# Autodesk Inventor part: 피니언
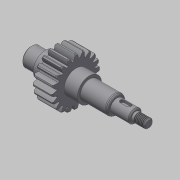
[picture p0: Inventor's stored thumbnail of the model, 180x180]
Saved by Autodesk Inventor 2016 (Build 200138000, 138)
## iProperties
Created: 2019-06
Part Number: 피니언
Material: 스테인리스강
Document SubType Name: Modeling
Designer: mduedu
Density: 1 g/cm^3
Appearance: 기본값
Author: mduedu
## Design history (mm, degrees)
sketch "스케치1"
  geometry: L1 (0, 0)-(13, 0); L2 (13, 0)-(13, 8.5); L3 (13, 8.5)-(0, 8.5); L4 (0, 8.5)-(0, 0); L5 (13, 0)-(53, 0); L6 (53, 0)-(53, 11); L7 (53, 11)-(13, 11); L8 (13, 11)-(13, 0); L9 (53, 0)-(78, 0); L10 (78, 0)-(78, 8.5); L11 (78, 8.5)-(53, 8.5); L12 (53, 8.5)-(53, 0); L13 (78, 0)-(95, 0); L14 (95, 0)-(95, 6); L15 (95, 6)-(78, 6); L16 (78, 6)-(78, 0); L17 (95, 0)-(107, 0); L18 (107, 0)-(107, 4); L19 (107, 4)-(95, 4); L20 (95, 4)-(95, 0)
  constraints: 40 end point, 10 parallel, 5 horizontal, 5 perpendicular
  dimensions: "d0" = 107 distance between parallel lines of L18 L4; "d2" = 78 distance between parallel lines of L10 L4; "d3" = 40 distance of L6.end L7.end; "d4" = 25 distance of L10.end L11.end; "d5" = 17 distance of L14.end L15.end; "d6" = 8 diameter of L19 L17; "d7" = 12 diameter of L15 L13; "d8" = 17 diameter of L11 L9; "d9" = 22 diameter of L7 L5; "d10" = 17 diameter of L3 L1
revolve "회전1" sketch "스케치1" stored, may be unused: angle "d11" = 90 deg
node "작업 평면1"
sketch "스케치2"
  geometry: C1 r 17.5 at (0, 0); C2 r 20 at (0, 0); C3 r 22 at (0, 0); 1 further point
  constraints: 3 centre point, 3 coincident
  dimensions: "d13" = 40 diameter of C2; "d15" = 44 diameter of C3; "d16" = 35 diameter of C1
extrude "돌출1" join sketch "스케치2" distance "d17" = 18; taper "d18" = 0 deg
sketch "스케치3"
  geometry: L1 (0, 0)-(22, 0); L2 (0, 0)-(0, 22); L3 (0.57, 0)-(0.57, 22); L4 (1.57, 0)-(1.57, 22); L5 (2.07, 0)-(2.07, 22); A1 r 22 centre (0, 0) between (22, 0) and (0, 22) reference; A2 r 9.495 centre (-7.411, 16.856) between (2.07, 17.377) and (0.57, 22); A3 r 9.495 centre (7.411, 16.856) between (-0.57, 22) and (-2.07, 17.377); A4 r 17.5 centre (0, 0) between (2.07, 17.377) and (-2.07, 17.377); A5 r 22.007 centre (0, 0) between (0.57, 22) and (-0.57, 22); 4 further points
  constraints: 11 point on circle, 10 end point, 6 parallel, 5 point on line, 4 centre point, 3 symmetric about line, 2 coincident, 1 horizontal, 1 perpendicular, 5 other
  dimensions: "d19" = 0.5 distance between parallel lines of L5 L4; "d21" = 1 distance between parallel lines of L3 L4; "d22" = 1.57 distance between parallel lines of L2 L4
extrude "돌출2" join sketch "스케치3" stored distance "d23" = 18; taper "d24" = 0 deg
chamfer "모따기1" distance "d25" = 1; stored, may be unused: second distance "d26" = 2, angle "d27" = 45 deg
fillet "모깎기1" dims "d31" = 0.3
chamfer "모따기2" distance "d32" = 1; stored, may be unused: second distance "d33" = 2, angle "d34" = 45 deg
node "작업 평면2"
sketch "스케치4"
  geometry: L1 (3.5, -2)-(-2.5, -2); L2 (-2.5, 2)-(3.5, 2); L3 (8.5, 8.5)-(8.5, -8.5) reference; A1 r 2 centre (3.5, 0) between (3.5, -2) and (3.5, 2); A2 r 2 centre (-2.5, 0) between (-2.5, 2) and (-2.5, -2); 1 further point
  constraints: 4 end point, 4 point on circle, 4 tangent, 2 centre point, 1 horizontal, 1 horizontal alignment, 1 parallel
  dimensions: "d35" = 3 distance edge to line of A1 L3; "d36" = 10 dimension on A2 A1; "d37" = 4 distance between parallel lines of L2 L1
extrude "돌출3" cut sketch "스케치4" distance "d38" = 2.5; taper "d39" = 0 deg
chamfer "모따기3" distance "d40" = 1.82; stored, may be unused: second distance "d41" = 2, angle "d42" = 30 deg
fillet "모깎기2" dims "d43" = 1, "d44" = 2
chamfer "모따기4" distance "d45" = 1; stored, may be unused: second distance "d46" = 2, angle "d47" = 30 deg
feature "스레드1" dims "d48" = 10, "d49" = 0
chamfer "모따기5" distance "d50" = 1; stored, may be unused: second distance "d51" = 2, angle "d52" = 30 deg
node "솔리드1"
pattern_circular "원형 패턴1" dims angle "d29" = 360 deg
other parameters: "d12" = -12
